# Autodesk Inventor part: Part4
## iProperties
Shininess: 64.0
Length Units: 11269
Angle Units: 11279
Time Units: 11290
Mass Units: 11283
Length Display Precision: 3
Angle Display Precision: 2
Compacted: True
Part Number: Part4
Document SubType Name: Modeling
Created: 2002-12
Designer: deepak
Density: 0.0
Volumn: 0.0
Area: 0.0
PropertySet Name: Model Information
Control State: 0
Master: False
Checked Out: False
Author: deepak
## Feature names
1. Extrusion1
2. Split1
3. Revolution1
4. Revolution2
